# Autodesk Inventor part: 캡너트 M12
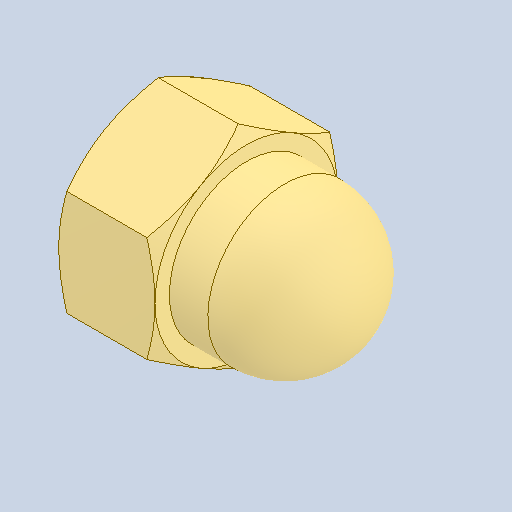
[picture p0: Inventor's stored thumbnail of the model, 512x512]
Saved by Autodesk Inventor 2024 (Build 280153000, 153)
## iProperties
Created: 2024-08
Part Number: 캡너트 M12
Material: 강철, 연강
Description: 6각 둥근캡 너트
Document SubType Name: Modeling
Designer: user
Density: 7.85 g/cm^3
Appearance: 기본값
Author: jhkim
Sending System: Autodesk Inventor 2025
Preprocessor: ST-DEVELOPER v20
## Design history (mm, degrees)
feature "Solid1"
node "솔리드1"
